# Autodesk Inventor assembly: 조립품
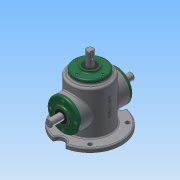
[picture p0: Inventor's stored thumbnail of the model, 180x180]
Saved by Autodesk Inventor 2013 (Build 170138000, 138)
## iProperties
Created: 2018-04
Part Number: 조립품
Document SubType Name: Assembly
Designer: Administrator
Author: Administrator
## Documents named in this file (16)
- C:\Users\Administrator\Desktop\480408V1010\조립품.iam
- C:\Users\Administrator\Desktop\480408V1010\본체.ipt
- C:\Users\Administrator\Desktop\480408V1010\볼트 M4.ipt
- 볼트 M4.ipt
- C:\Users\Administrator\Desktop\480408V1010\메인 축.ipt
- 메인 축.ipt
- C:\Users\Administrator\Desktop\480408V1010\키 5x5.ipt
- C:\Users\Administrator\Desktop\480408V1010\메인 베벨기어.ipt
- C:\Users\Administrator\Desktop\480408V1010\베어링 6203.ipt
- C:\Users\Administrator\Desktop\480408V1010\커버.ipt
- C:\Users\Administrator\Desktop\480408V1010\오일 실.ipt
- 오일 실.ipt
- C:\Users\Administrator\Desktop\480408V1010\서브 축.ipt
- 서브 축.ipt
- C:\Users\Administrator\Desktop\480408V1010\서브 베벨기어.ipt
- C:\Users\Administrator\Desktop\480408V1010\키 4x4.ipt
